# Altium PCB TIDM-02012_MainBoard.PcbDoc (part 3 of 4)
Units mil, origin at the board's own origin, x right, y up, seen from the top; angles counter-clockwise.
Board outline 6550 x 5100 mil, 4 copper layers (Top Layer, Layer 1, Layer 2, Bottom Layer), stack 81.2 mil thick; 300 components, 157 nets, 916 pads, 350 vias.
Unrouted connection lines stored in the file: 93.
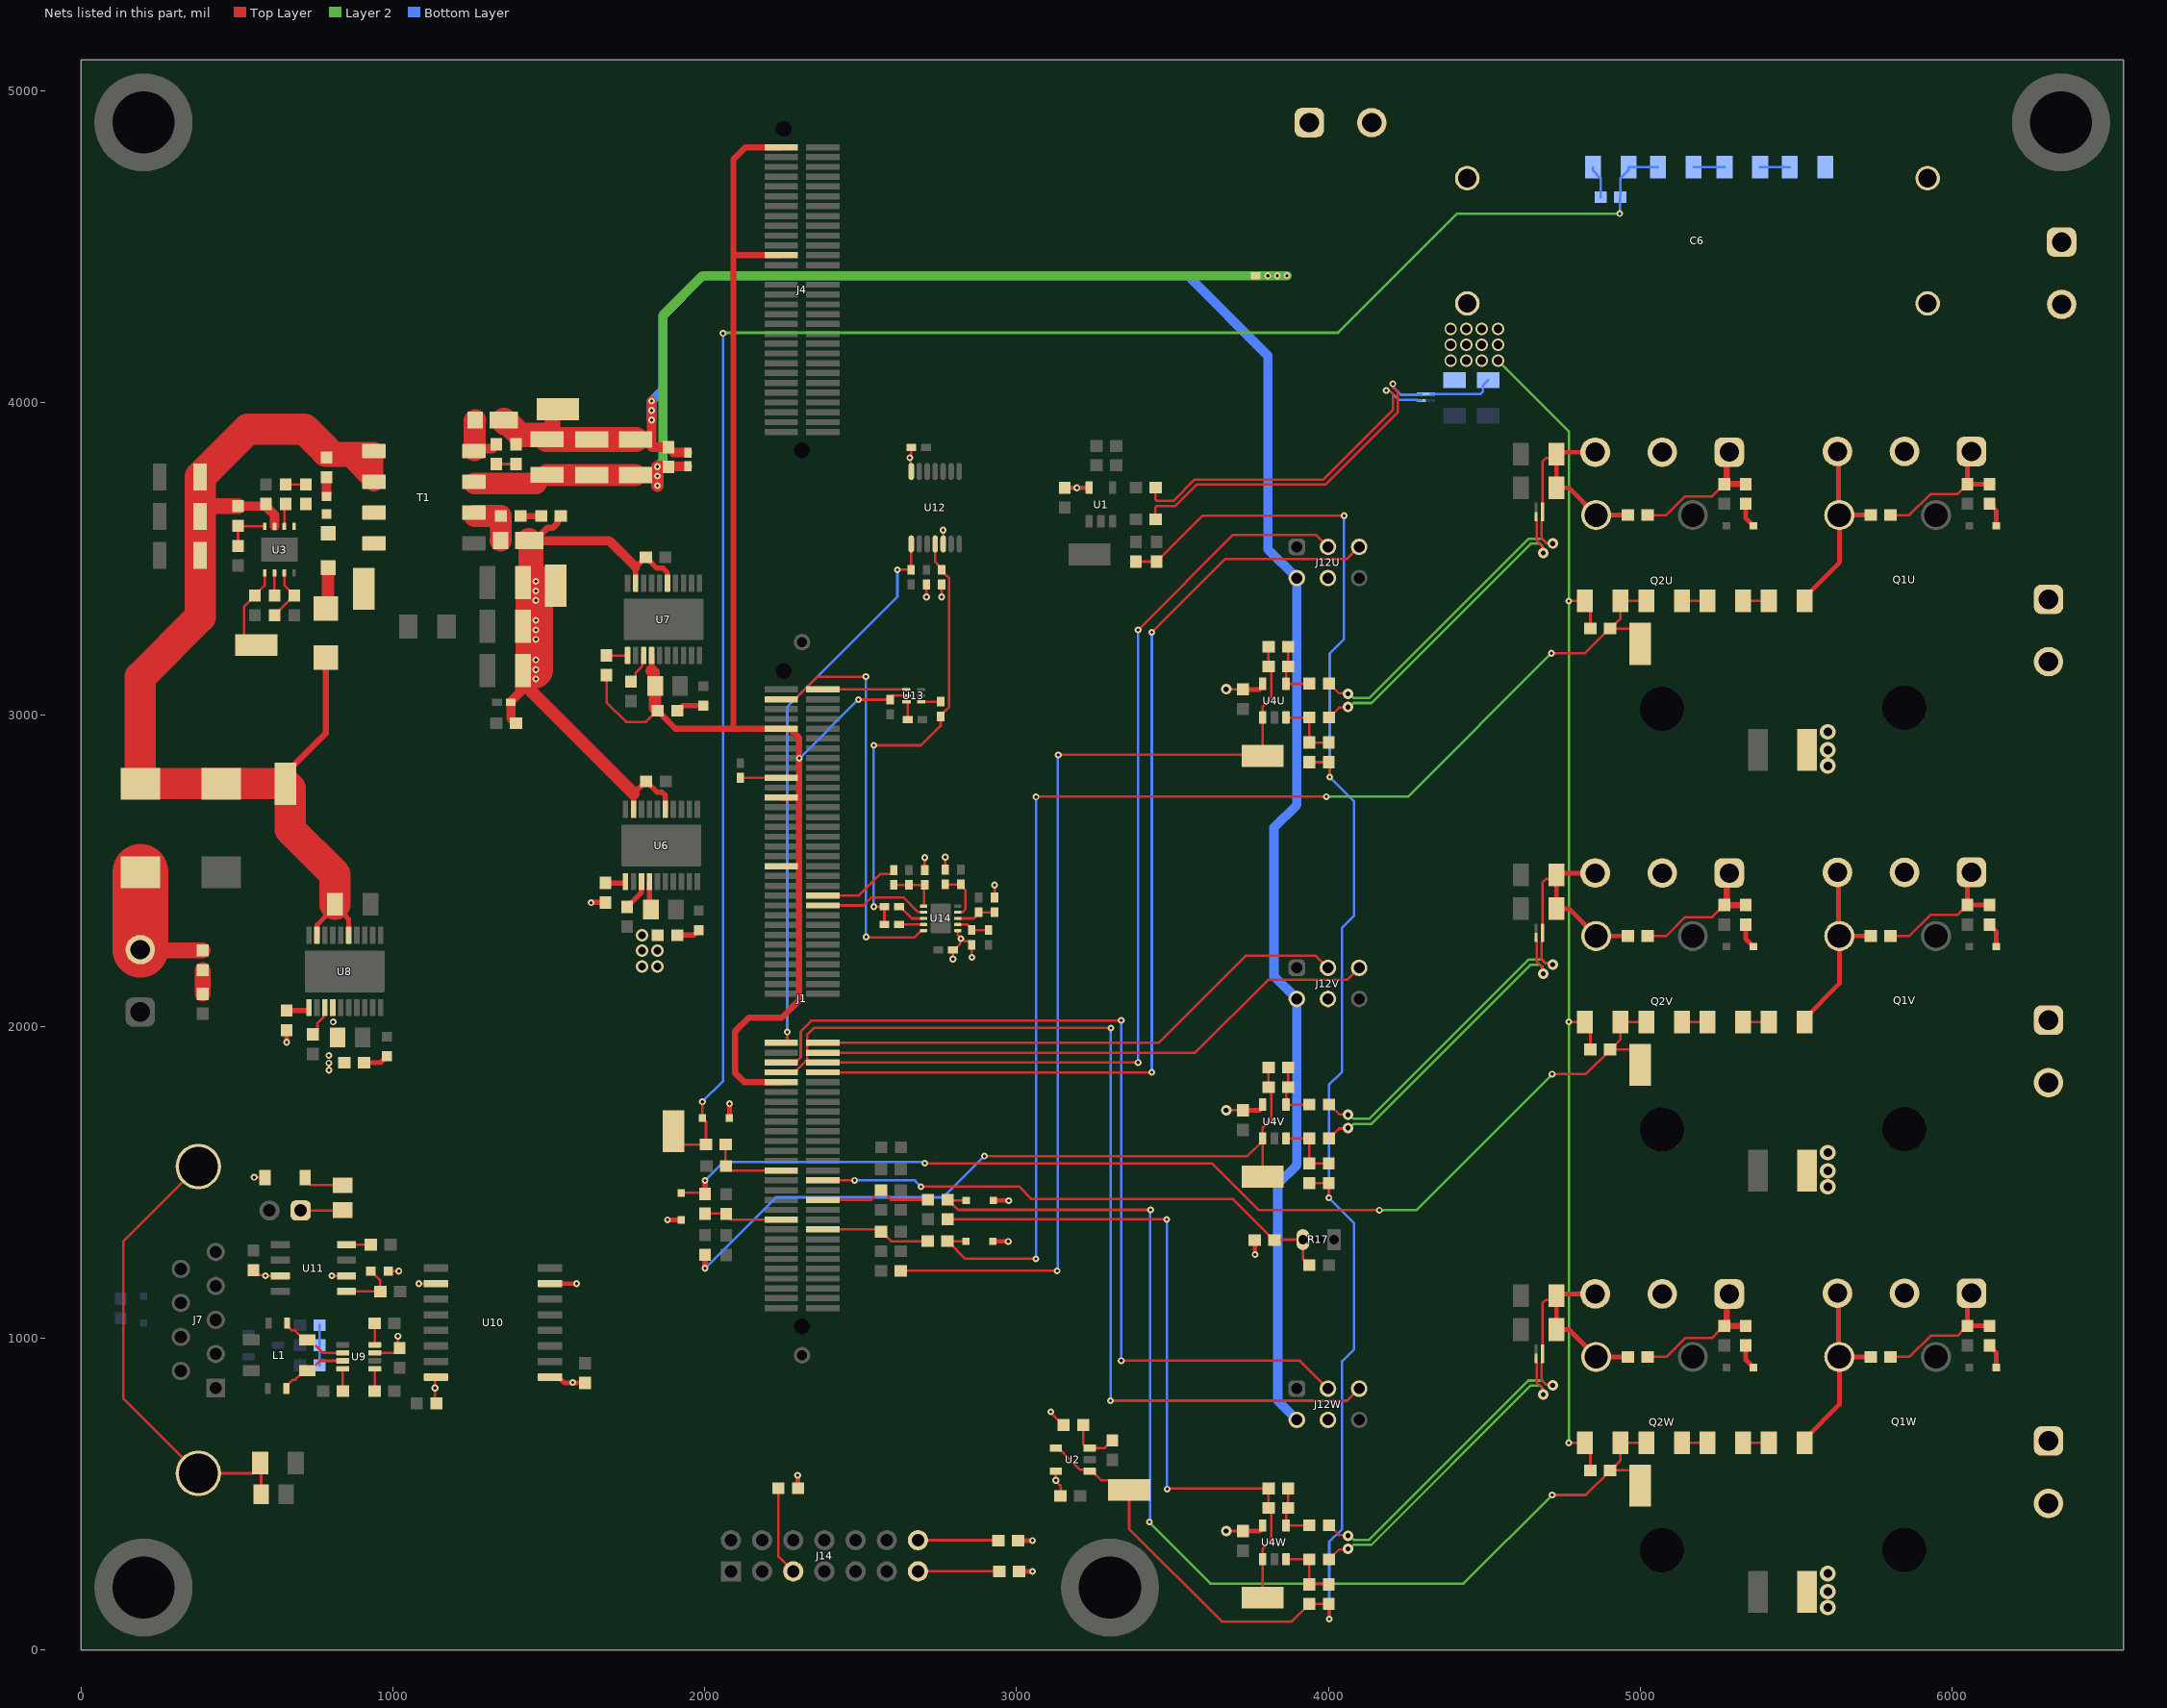
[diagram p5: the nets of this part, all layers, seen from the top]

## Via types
v1: diameter 22, hole 10, Top Layer to Bottom Layer, tented both sides, 245 vias
v2: diameter 40, hole 28, Top Layer to Bottom Layer, tented both sides, 60 vias
v3: diameter 34, hole 16, Top Layer to Bottom Layer, tented both sides, 22 vias
v4: diameter 22, hole 10, Top Layer to Bottom Layer, 9 vias
v5: diameter 50, hole 28, Top Layer to Bottom Layer, tented both sides, 9 vias
v6: diameter 40, hole 25, Top Layer to Bottom Layer, tented both sides, 5 vias

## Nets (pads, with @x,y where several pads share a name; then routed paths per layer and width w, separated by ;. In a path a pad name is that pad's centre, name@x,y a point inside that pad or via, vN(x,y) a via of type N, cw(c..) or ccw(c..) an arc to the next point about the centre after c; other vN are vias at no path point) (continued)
NetC5_1: C5.1 D1.2 R8.1 R11.2 R75.1 TP1.1 | length 6054.7
  Top Layer w8: TP1.1@1899.54,1664.1 1899.54,1652 1930.54,1621 R75.1@2004,1621 2004,1694.39 D1.2@1992.39,1706 v1(1992.39,1758.11)
  Layer 2 w8: v1(2059,4223) 2061.08,4225.08 4030.93,4225.08 4412.85,4607 v1(4935,4607)
  Bottom Layer w8: v1(1992.39,1758.11) 2059,1824.72 v1(2059,4223) ; v1(4935,4607) 4935,4658.5 C5.1@4936.5,4660 4936.5,4719.69 4962.55,4745.75 R11.2@4962.55,4756.57 R8.1@5057.36,4756.57
NetC12_1: C12.1 R18.1 | length 63.2
  Top Layer w8: C12.1@1331.69,3803.76 R18.1@1394.84,3803.76
NetC12_2: C12.2 D3.2 T1.5 | length 179.9
  Top Layer w30: T1.5@1259.55,3845.02 1262.15,3847.62 1267.58,3853.05 1318.97,3853.05 1331.69,3865.77 C12.2@1331.69,3866.75
  Top Layer w70: T1.5@1262.15,3847.62 1262.15,3942.77 D3.2@1264.3,3944.93
NetC18U_1: C18U.1 R29U.2 R43U.1 TP5U.1 U4U.1 | length 3180.4
  Top Layer w8: R43U.1@2628.5,1216 v4(3130.52,1216) ; v4(3133.78,2871) 3786.41,2871 TP5U.1@3789.6,2867.81 U4U.1@3789.6,2990.82 3789.6,3026.05 3816.84,3053.29 3816.84,3146.61 R29U.2@3808.5,3154.95 C18U.1@3808.5,3217.95
  Bottom Layer w8: v4(3130.52,1216) 3132.15,1217.63 3132.15,2869.37 v4(3133.78,2871)
NetC18U_2: C18U.2 R29U.1 R31U.2 U4U.4 | length 196.8
  Top Layer w8: C18U.2@3871.5,3217.95 R29U.1@3871.5,3154.95 3864.4,3147.86 U4U.4@3864.4,3099.09 3938.13,3099.09 R31U.2@3939,3099.95
NetC18V_1: C18V.1 R29V.2 R43V.1 TP5V.1 U4V.1 | length 2366.3
  Top Layer w8: v1(2897.21,1583.98) 3740.64,1583.98 U4V.1@3789.6,1632.94 ; TP5V.1@3789.6,1517.81 U4V.1@3789.6,1632.94 ; C18V.1@3808.5,1867.95 R29V.2@3808.5,1804.95 3816.84,1796.61 3816.84,1703.29 3789.6,1676.05 U4V.1@3789.6,1640.82 U4V.1@3789.6,1632.94
  Top Layer w20: v1(2001,1224.07) R43V.1@2001,1267.5
  Bottom Layer w8: v1(2001,1224.07) 2228.58,1451.65 2764.88,1451.65 v1(2897.21,1583.98)
NetC18V_2: C18V.2 R29V.1 R31V.2 U4V.4 | length 196.8
  Top Layer w8: C18V.2@3871.5,1867.95 R29V.1@3871.5,1804.95 3864.4,1797.86 U4V.4@3864.4,1749.09 3938.13,1749.09 R31V.2@3939,1749.95
NetC18W_1: C18W.1 R29W.2 R43W.1 TP5W.1 U4W.1 | length 2260.5
  Top Layer w8: R43W.1@2778.94,1381.41 v4@3482,1381.41 ; v4(3483,516) 3484.95,517.95 C18W.1@3808.5,517.95 R29W.2@3808.5,454.95 3816.84,446.61 3816.84,353.29 3789.6,326.05 U4W.1@3789.6,290.82 TP5W.1@3789.6,167.81 TP5W.1@3790.2,168.41
  Bottom Layer w8: v4(3482,1381) 3482.5,1380.5 3482.5,516.5 v4(3483,516)
NetC18W_2: C18W.2 R29W.1 R31W.2 U4W.4 | length 196.8
  Top Layer w8: C18W.2@3871.5,517.95 R29W.1@3871.5,454.95 3864.4,447.86 U4W.4@3864.4,399.09 3938.13,399.09 R31W.2@3939,399.95
NetC19U_1: C19U.1 D7U.2 R28U.1 R30U.2 R45U.1 TP4U.1 | length 4224.7
  Top Layer w8: R45U.1@2778.02,1311.27 2779.01,1311.27 R45U.1@2779.48,1310.79 ; D7U.2@2837.69,1310.79 R45U.1@2779.48,1310.79 ; v4@3062.39,1255.02 2835.26,1255.02 R45U.1@2779.48,1310.79 ; v4(3062.62,2735.99) 3063.63,2737 v4(3993.78,2737) ; v1(4715.99,3197.01) 4823.73,3197.01 4902.66,3275.94 C19U.1@4903.64,3275.94 C19U.1@4904.63,3275.94 ; TP4U.1@5000.1,3226.72 5000.1,3244.94 4969.1,3275.94 C19U.1@4904.63,3275.94 ; R28U.1@5019.78,3364.52 R30U.2@4937.11,3364.52 4937.11,3308.42 C19U.1@4904.63,3275.94
  Layer 2 w8: v4(3993.78,2737) 4255.98,2737 v1(4715.99,3197.01)
  Bottom Layer w8: v4(3062.39,1254.14) 3062.62,1254.38 v4(3062.62,2735.99)
NetC19V_1: C19V.1 D7V.2 R28V.1 R30V.2 R45V.1 TP4V.1 | length 3638.4
  Top Layer w8: D7V.2@1925.13,1465.8 1997.79,1465.8 R45V.1@2001,1462.58 ; v1(2705.72,1561.53) 2706.26,1560.98 3626.96,1560.98 3777.44,1410.5 v1(4163.84,1410.5) ; v1(4717.96,1847.01) 4825.7,1847.01 C19V.1@4904.63,1925.94 ; C19V.1@4903.64,1925.94 C19V.1@4904.63,1925.94 ; TP4V.1@5000.1,1876.72 5000.1,1894.94 4969.1,1925.94 C19V.1@4904.63,1925.94 ; R28V.1@5019.78,2014.52 R30V.2@4937.11,2014.52 4937.11,1958.42 C19V.1@4904.63,1925.94
  Top Layer w20: R45V.1@2001,1462.58 v1(2001,1506.02)
  Layer 2 w8: v1(4163.84,1410.5) 4281.45,1410.5 v1(4717.96,1847.01)
  Bottom Layer w8: v1(2001,1506.02) 2059.98,1565 2702.25,1565 v1(2705.72,1561.53)
NetC19W_1: C19W.1 D7W.2 R28W.1 R30W.2 R45W.1 TP4W.1 | length 3747.5
  Top Layer w8: R45W.1@2778.94,1443.92 2779.93,1443.92 R45W.1@2781.85,1442 ; D7W.2@2838.69,1442 R45W.1@2781.85,1442 ; v4(3429.82,1411.5) 2812.35,1411.5 R45W.1@2781.85,1442 ; v1(4717.96,497.01) 4825.7,497.01 C19W.1@4904.63,575.94 ; C19W.1@4903.64,575.94 C19W.1@4904.63,575.94 ; TP4W.1@5000.1,526.72 5000.1,544.94 4969.1,575.94 C19W.1@4904.63,575.94 ; R28W.1@5019.78,664.52 R30W.2@4937.11,664.52 4937.11,608.42 C19W.1@4904.63,575.94
  Layer 2 w8: v4(3426.19,410.47) 3426.19,408.81 3622,213 4433.95,213 v1(4717.96,497.01)
  Bottom Layer w8: v4(3426.19,410.47) 3428.01,412.29 3428.01,1409.68 v4(3429.82,1411.5)
NetC21U_1: C21U.1 R32U.2 R33U.2 U4U.3 | length 217.9
  Top Layer w8: U4U.3@3864.4,2990.82 R32U.2@3939,2990.82 R33U.2@3939,2910.5 C21U.1@4001.99,2910.5
NetC21V_1: C21V.1 R32V.2 R33V.2 U4V.3 | length 217.9
  Top Layer w8: U4V.3@3864.4,1640.82 R32V.2@3939,1640.82 R33V.2@3939,1560.5 C21V.1@4001.99,1560.5
NetC21W_1: C21W.1 R32W.2 R33W.2 U4W.3 | length 217.9
  Top Layer w8: U4W.3@3864.4,290.82 R32W.2@3939,290.82 R33W.2@3939,210.5 C21W.1@4001.99,210.5
NetC27_1: C27.1 D9.2 J5.2 | length 449.7
  Top Layer w50: J5.2@190,2246.15 192.37,2243.78 C27.1@389.97,2243.78
  Top Layer w180: J5.2@190,2246.15 D9.2@190,2494.87
NetC27_2: C27.2 C34.1 | length 76.8
  Top Layer w50: C34.1@389.97,2104 C27.2@389.97,2180.79
NetC31_1: C31.1 U6.3 | length 100.5
  Top Layer w17: C31.1@1750.73,2383 1750.73,2383.99 1796.95,2430.21 1796.95,2463.99 U6.3@1797.18,2464.22
NetC32_1: C32.1 R19.1 | length 62.3
  Top Layer w30: C32.1@786.82,3699.36 R19.1@786.82,3761.65
NetC32_2: C32.2 D18.2 R37.2 T1.1 T1.2 TP6.1 U3.1
NetC33_1: C33.1 R21.1 | length 66.2
  Top Layer w20: C33.1@1409.49,3637.4 1409.73,3637.16 1475.26,3637.16 R21.1@1475.5,3636.91
NetC33_2: C33.2 D10.2 T1.7 | length 163.9
  Top Layer w70: T1.7@1262.15,3637.4 C33.2@1346.5,3637.4 1346.5,3559.27 D10.2@1345.49,3558.27
NetC36_1: C36.1 TP9.1 U3.5 | length 280.8
  Top Layer w8: TP9.1@562,3223 553,3223 522,3254 522,3345.71 557.34,3381.05 C36.1@557.34,3382.03 557.34,3383.02 588.76,3414.43 U3.5@588.76,3454.33
NetC42_1: C42.1 U7.3 | length 100.1
  Top Layer w8: C42.1@1763.61,3106.18 1778.32,3120.88 1778.32,3134.17 1799.34,3155.19 1799.34,3184.81 U7.3@1804.07,3189.54
NetC46_1: C46.1 U8.3 | length 117.6
  Top Layer w8: C46.1@743.26,1974.7 757.96,1989.4 757.96,2009.97 767,2019 767.17,2019 776.92,2028.75 776.92,2055.4 U8.3@781.65,2060.14
  Top Layer w16: C46.1@743.26,1974.7 743.26,1975.68 C46.1@753.96,1986.38
NetC48_2: C48.2 R50.1 R52.2 | length 129.1
  Bottom Layer w8: R50.1@764.99,912.85 C48.2@764.99,977.6 R52.2@764.99,1042
NetC55_1: C55.1 U13.3 | length 60.1
  Top Layer w8: U13.3@2646.98,3041.11 2649.86,3041.11 2650.78,3040.19 C55.1@2650.78,2984.32
NetC57_1: C57.1 R65.1 U14.2 | length 108.3
  Top Layer w8: U14.2@2811.93,2326.78 2842.94,2326.78 2856.72,2313 R65.1@2856.72,2309.06 C57.1@2910.58,2309.06
NetC58_1: C58.1 R70.1 U14.4 | length 164.3
  Top Layer w8: R70.1@2771.43,2455.46 C58.1@2821.77,2455.46 2821.77,2451.52 2836.22,2437.07 2836.22,2375.84 2827.46,2367.07 2812.85,2367.07 U14.4@2811.93,2366.15
NetD2U_2: D2U.2 R13U.1 | length 79.7
  Top Layer w15: R13U.1@6120.33,3676.48 6120.33,3675.5 6142.45,3653.38 D2U.2@6142.45,3605.95
NetD2V_2: D2V.2 R13V.1 | length 79.7
  Top Layer w15: R13V.1@6120.33,2326.48 6120.33,2325.5 6142.45,2303.38 D2V.2@6142.45,2255.95
NetD2W_2: D2W.2 R13W.1 | length 79.7
  Top Layer w15: R13W.1@6120.33,976.48 6120.33,975.5 6142.45,953.38 D2W.2@6142.45,905.95
NetD5U_2: D5U.2 R20U.1 | length 80.7
  Top Layer w15: R20U.1@5338.84,3676.48 5338.84,3630.56 D5U.2@5363.44,3605.95
NetD5V_2: D5V.2 R20V.1 | length 80.7
  Top Layer w15: R20V.1@5338.84,2326.48 5338.84,2280.56 D5V.2@5363.44,2255.95
NetD5W_2: D5W.2 R20W.1 | length 80.7
  Top Layer w15: R20W.1@5338.84,976.48 5338.84,930.56 D5W.2@5363.44,905.95
NetD6_1: D6.1 D18.1 | length 133.8
  Top Layer w40: D6.1@784.49,3340.74 792.3,3348.55 D18.1@792.3,3471.32
NetD12_2: D12.2 R42.1 | length 75.3
  Top Layer w17: R42.1@1912.34,2292.81 1965.39,2292.81 D12.2@1981.14,2308.56
NetD13_2: D13.2 R47.1 | length 90.1
  Top Layer w17: R47.1@1912.34,3012.94 1913.32,3012.94 1929.07,3028.69 D13.2@1995.9,3028.69
NetD15_1: D15.1 R56.2 | length 133.4
  Top Layer w8: D15.1@718.74,1514.96 718.74,1508.95 737.1,1490.59 R56.2@838.51,1490.59
NetD17_2: D17.2 R74.1 | length 82.4
  Top Layer w16: R74.1@907.09,1883.22 959.72,1883.22 D17.2@980.73,1904.23
NetJ1_102: J1.102 R79.1 | length 131.1
  Top Layer w8: R79.1@2114,2797.48 J1.102@2245.14,2797.48
NetJ6_1: J6.1 R56.1 | length 134.7
  Top Layer w8: J6.1@704.27,1409.45 837.38,1409.45 R56.1@838.51,1410.59
NetJ14_5: J14.5 R76.2 | length 286.7
  Top Layer w8: R76.2@2236.5,519 2236.5,299.5 J14.5@2284,252
NetJ14_13: J14.13 R78.2 | length 261
  Top Layer w8: J14.13@2684,252 R78.2@2945.01,252
NetJ14_14: J14.14 R77.1 | length 258.5
  Top Layer w8: J14.14@2684,352 2941.05,352 R77.1@2942.06,350.99
NetL1_1: L1.1 R54.1 U9.7 | length 222.9
  Top Layer w8: R54.1@658.09,838.21 658.09,846.09 678.48,866.47 686.75,866.47 716.28,896 L1.1@725.13,896 733.99,896 765.41,927.42 U9.7@839.39,927.42
NetL1_2: L1.2 R49.1 U9.6 | length 222.9
  Top Layer w8: R49.1@660.57,1048.21 660.57,1040.34 675.91,1025 685.7,1025 716.28,994.43 L1.2@725.13,994.43 733.99,994.43 775.41,953.01 U9.6@839.39,953.01
NetQ1U_1: Q1U.1 R13U.2 R15U.2 R16U.2 | length 469.3
  Top Layer w8: R16U.2@5802.99,3640 5863.82,3640 5931.8,3707.98 6018.26,3707.98 6034.07,3723.79 6035.06,3723.79 6049.76,3738.49 R15U.2@6049.76,3739.47
  Top Layer w15: Q1U.1@6063,3844.2 6049.76,3830.96 R15U.2@6049.76,3739.47 R13U.2@6120.33,3739.47
NetQ1V_1: Q1V.1 R13V.2 R15V.2 R16V.2 | length 469.3
  Top Layer w8: R16V.2@5802.99,2290 5863.82,2290 5931.8,2357.98 6018.26,2357.98 6034.07,2373.79 6035.06,2373.79 6049.76,2388.49 R15V.2@6049.76,2389.47
  Top Layer w15: Q1V.1@6063,2494.2 6049.76,2480.96 R15V.2@6049.76,2389.47 R13V.2@6120.33,2389.47
NetQ1W_1: Q1W.1 R13W.2 R15W.2 R16W.2 | length 469.3
  Top Layer w8: R16W.2@5802.99,940 5863.82,940 5931.8,1007.98 6018.26,1007.98 6034.07,1023.79 6035.06,1023.79 6049.76,1038.49 R15W.2@6049.76,1039.47
  Top Layer w15: Q1W.1@6063,1144.2 6049.76,1130.96 R15W.2@6049.76,1039.47 R13W.2@6120.33,1039.47
NetQ2U_1: Q2U.1 R20U.2 R22U.2 R23U.2 | length 465.6
  Top Layer w8: R23U.2@5023.99,3640 5083.82,3640 5144.05,3700.23 5230.86,3700.23 5254.42,3723.79 5255.4,3723.79 5270.1,3738.49 R22U.2@5270.1,3739.47
  Top Layer w20: Q2U.1@5285.99,3841.83 5278.05,3833.89 5278.05,3747.41 R22U.2@5270.1,3739.47 R20U.2@5338.84,3739.47
NetQ2V_1: Q2V.1 R20V.2 R22V.2 R23V.2 | length 465.6
  Top Layer w8: R23V.2@5023.99,2290 5083.82,2290 5144.05,2350.23 5230.86,2350.23 5254.42,2373.79 5255.4,2373.79 5270.1,2388.49 R22V.2@5270.1,2389.47
  Top Layer w20: Q2V.1@5285.99,2491.83 5278.05,2483.89 5278.05,2397.41 R22V.2@5270.1,2389.47 R20V.2@5338.84,2389.47
NetQ2W_1: Q2W.1 R20W.2 R22W.2 R23W.2 | length 465.6
  Top Layer w8: R23W.2@5023.99,940 5083.82,940 5144.05,1000.23 5230.86,1000.23 5254.42,1023.79 5255.4,1023.79 5270.1,1038.49 R22W.2@5270.1,1039.47
  Top Layer w20: Q2W.1@5285.99,1141.83 5278.05,1133.89 5278.05,1047.41 R22W.2@5270.1,1039.47 R20W.2@5338.84,1039.47
NetR5_1: R5.1 R12.2 U2.3 | length 170.4
  Top Layer w8: R5.1@3213.97,721.37 3213.97,660.54 3226.73,647.77 U2.3@3234.61,647.77 3282.88,647.77 3291.79,656.68 3292.77,656.68 3307.47,671.38 R12.2@3307.47,672.37
NetR6_1: R6.1 R7.2 | length 94.2
  Bottom Layer w8: R7.2@5385.07,4756.57 R6.1@5479.25,4756.57
NetR7_1: R7.1 R8.2 | length 99.4
  Bottom Layer w8: R8.2@5171.53,4756.57 R7.1@5270.9,4756.57
NetR26U_1: R26U.1 R27U.2 | length 82
  Top Layer w8: R27U.2@5330.81,3364.52 R26U.1@5412.86,3364.52
NetR26V_1: R26V.1 R27V.2 | length 82
  Top Layer w8: R27V.2@5330.81,2014.52 R26V.1@5412.86,2014.52
NetR26W_1: R26W.1 R27W.2 | length 82
  Top Layer w8: R27W.2@5330.81,664.52 R26W.1@5412.86,664.52
NetR27U_1: R27U.1 R28U.2 | length 82.7
  Top Layer w8: R28U.2@5133.96,3364.52 R27U.1@5216.64,3364.52
NetR27V_1: R27V.1 R28V.2 | length 82.7
  Top Layer w8: R28V.2@5133.96,2014.52 R27V.1@5216.64,2014.52
NetR27W_1: R27W.1 R28W.2 | length 82.7
  Top Layer w8: R28W.2@5133.96,664.52 R27W.1@5216.64,664.52
NetR34_1: R34.1 R38.2 U3.4 | length 150.9
  Top Layer w8: R38.2@503.34,3541.26 R34.1@503.34,3605.91 505.31,3603.94 U3.4@588.76,3603.94
NetR35_1: R35.1 R39.2 U3.7 | length 175.6
  Top Layer w8: R35.1@620.22,3319.04 620.22,3320.02 666.55,3366.35 668.54,3366.35 683.24,3381.05 R39.2@683.24,3382.03 683.24,3383.02 651.75,3414.51 U3.7@651.75,3454.33
NetR35_2: R35.2 U3.6 | length 72.3
  Top Layer w8: R35.2@620.25,3382.06 U3.6@620.25,3454.33
NetR36_1: R36.1 U3.2 | length 73.3
  Top Layer w8: U3.2@651.75,3603.94 651.75,3671.3 R36.1@655.98,3675.53
NetR36_2: R36.2 R37.1 | length 64.7
  Top Layer w8: R36.2@655.98,3738.52 R37.1@720.65,3738.52
NetR41_1: R41.1 U6.1 | length 68.5
  Top Layer w17: R41.1@1681.16,2460.36 1745.64,2460.36 1746,2460.72 U6.1@1746,2464.22
NetR46_1: R46.1 U7.1 | length 67.9
  Top Layer w8: R46.1@1685.04,3189.69 1685.19,3189.54 U7.1@1752.89,3189.54
NetR48_1: R48.1 U8.1 | length 79.5
  Top Layer w16: R48.1@659.59,2051.01 729.61,2051.01 730.47,2051.87 U8.1@730.47,2060.14
NetR51_2: R51.2 U9.1 | length 71.9
  Top Layer w8: R51.2@941.5,830 941.75,830.24 U9.1@941.75,901.83
NetR53_2: R53.2 U9.4 | length 69.6
  Top Layer w8: U9.4@941.75,978.6 R53.2@941.75,1048.21
NetR55_2: R55.2 U9.8 | length 71.8
  Top Layer w8: R55.2@839.39,830 U9.8@839.39,901.83
NetR57_1: R57.1 R58.2 U11.1 | length 186.2
  Top Layer w8: U11.1@851.3,1150 928.95,1150 R58.2@959.72,1150 959.72,1184.22 R57.1@928.95,1214.99
NetR59_2: R59.2 U11.4 | length 77.7
  Top Layer w8: U11.4@851.3,1300 R59.2@928.95,1300
NetR64_1: R64.1 U13.4 | length 62.8
  Top Layer w8: U13.4@2694.22,3041.11 2756.35,3041.11 R64.1@2756.81,3041.57
NetR66_1: R66.1 U14.9 | length 78.2
  Top Layer w8: R66.1@2623.53,2326.94 2623.61,2326.86 2701.62,2326.86 U14.9@2701.7,2326.78
NetR67_1: R67.1 U14.8 | length 93.7
  Top Layer w8: R67.1@2623.53,2383.87 2627.47,2383.87 2664.87,2346.47 U14.8@2701.7,2346.47
NetR68_1: R68.1 R71.2 U14.3 | length 128.2
  Top Layer w8: U14.3@2811.93,2346.47 2862.63,2346.47 2878.37,2362.21 R71.2@2878.37,2366.15 ; R71.2@2878.37,2366.15 R68.1@2929.72,2366.15
NetR69_1: R69.1 R72.2 R73.1 U14.6 | length 170.4
  Top Layer w8: R73.1@2605.9,2454.08 R72.2@2655.12,2454.08 R69.1@2705.72,2454.08 2703.71,2452.07 2703.71,2386.76 2702.79,2385.84 U14.6@2701.7,2385.84
P5V_MCU: C41.1 C54.1 J1.48 J1.84 J1.98 J1.112 J4.158 J4.180 R46.2 R47.2 U7.4 U13.2 | length 5040.2
  Top Layer w8: R46.2@1685.04,3126.69 1685.04,3039.35 1747.83,2976.57 1811.74,2976.57 1820.86,2985.68 1821.09,2985.68 1841.04,3005.63 R47.2@1841.04,3012.94 ; v1(2493.33,3048) C54.1@2595,3048 2595,3051.94 2603.86,3060.8 U13.2@2646.98,3060.8
  Top Layer w17: U7.4@1829.66,3189.54 1829.89,3189.31 1829.89,3140.03
  Top Layer w20: R47.2@1841.04,3021.24 1842.03,3021.24 1859.03,3004.24 1859.03,3002.41 1906.48,2954.96 2092.35,2954.96 ; J1.48@2245.14,1821.1 2127.28,1821.1 2096.84,1851.54 2096.84,1983.84 2141,2028 2247,2028 2303,2084 2303,2514.22 ; J1.84@2245.14,2514.02 2302.79,2514.02 2303,2514.22 ; J1.98@2245.14,2734.49 2303,2734.49 ; J4.158@2245.14,4473.58 2092,4473.58 ; J4.180@2245.14,4820.04 2131.04,4820.04 2092,4781 2092,4473.58 ; 2092,4473.58 2092,2955.31 2092.35,2954.96 ; 2092.35,2954.96 J1.112@2245.14,2954.96 2245.3,2954.8 2272.72,2954.8 2303,2924.52 v1(2303,2860.47) 2303,2734.49 ; 2303,2514.22 2303,2734.49
  Top Layer w40: 1829.66,3140.26 1829.89,3140.03 1836.04,3133.87 1836.04,3096.69 C41.1@1841.04,3091.69 R47.2@1841.04,3021.24
  Bottom Layer w8: v1(2303,2860.47) 2304.4,2860.47 2491.93,3048 v1(2493.33,3048)
PGND: C5.2 C6.1 C6.2 C15.2 C16.2 C17.2 C19U.2 C19V.2 C19W.2 C22.2 D4.2 J3.1 J3.2 NT2.1 R1.1 R2.1 R11.1 R30U.1 R30V.1 R30W.1 R44.2 T1.6 | length 7636.1
  Top Layer w8: v1(4771.34,664.52) R30W.1@4822.93,664.52 4840.65,646.8 C19W.2@4840.65,575.94 ; v1(4771.34,2014.52) R30V.1@4822.93,2014.52 4840.65,1996.8 C19V.2@4840.65,1925.94 ; v1(4771.34,3364.52) R30U.1@4822.93,3364.52 4840.65,3346.8 C19U.2@4840.65,3275.94
  Top Layer w30: C16.2@1778.44,3768.48 1788.88,3778.91 1846.84,3778.91 v1@1846.84,3793.92 ; C22.2@1884.1,3793.99 C22.2@1884.1,3794.97 1885.38,3796.25 1945.25,3796.25 D4.2@1946,3797
  Top Layer w40: v1(1848.13,3795.21) 1882.88,3795.21 C22.2@1884.1,3793.99 ; v1@1848.25,3765.21 v1(1848.36,3734.32)
  Top Layer w70: T1.6@1262.15,3741.07 1457.8,3741.07 ; C15.2@1494.11,3768.64 1494.27,3768.48 C16.2@1778.44,3768.48
  Layer 2 w8: v2(4544.01,4135.68) 4771.34,3908.35 v1(4771.34,3364.52) v1(4771.34,2014.52) v1(4771.34,664.52)
  Layer 2 w30: v1(1848.13,3795.21) 1865.71,3812.78 1865.71,4279.71 1993.81,4407.81 3609.63,4407.81 3806.11,4407.96 3836.11,4407.98 v1(3867,4408) ; v1@1848.26,3795.21 1848.31,3765.21 v1(1848.36,3734.32)
  Bottom Layer w8: NT2.1@4328,4028 4487.81,4028 4495.5,4035.69 4495.5,4055.57 R2.1@4513.02,4073.09 ; R11.1@4848.38,4756.57 4848.38,4745.75 4873.5,4720.63 C5.2@4873.5,4660
  other v1: 1848.13,3765.21 3806.11,4407.77 3836.11,4407.77
  other v2: 4392.51,4135.68 4442.26,4135.68 4492.01,4135.68 4392.51,4186.68 4442.26,4186.68 4492.01,4186.68 4544.01,4186.68 4392.51,4236.68 4442.26,4236.68 4492.01,4236.68 4544.01,4236.68
PWM1A: J1.49 J12U.5 | length 3244.5
  Top Layer w8: J1.49@2379,1852.6 v1@3434,1852.6 ; v1(3433.95,3263.95) 3669.43,3499.43 4060.43,3499.43 J12U.5@4099,3538
  Bottom Layer w8: v1(3434,1853) v1@3433.98,3263.93
PWM1B: J1.51 J12U.3 | length 3150
  Top Layer w8: J1.51@2379,1884.09 v1(3390,1884.09) ; v1(3390,3272) 3694.57,3576.57 3960.43,3576.57 J12U.3@3999,3538
  Bottom Layer w8: v1(3390,1884.09) v1(3390,3272)
PWM2A: J1.53 J12V.5 | length 1832.8
  Top Layer w8: J1.53@2379,1915.59 3573.35,1915.59 3807.18,2149.43 4060.43,2149.43 J12V.5@4099,2188
PWM2B: J1.55 J12V.3 | length 1751.7
  Top Layer w8: J1.55@2379,1947.09 3455,1947.09 3734.49,2226.57 3960.43,2226.57 J12V.3@3999,2188
PWM3A: J1.50 J12W.5 | length 3174
  Top Layer w8: J1.50@2245.14,1852.6 2288.6,1852.6 2328.68,1892.68 2328.68,1972.95 2351.73,1996 v1@3303,1996 ; v1(3301.45,799.43) 4060.43,799.43 J12W.5@4099,838
  Bottom Layer w8: v1(3301.45,799.43) 3302.23,800.2 3302.23,1994.23 v1(3303,1995)
PWM3B: J1.52 J12W.3 | length 2986.3
  Top Layer w8: J1.52@2245.14,1884.09 2291.09,1884.09 2308,1901 2308,1984 2342,2018 v1@3336,2018 ; v1(3336.02,927.87) 3909.13,927.87 J12W.3@3999,838
  Bottom Layer w8: v1(3336.02,927.87) v1(3336,2019)
S_1U: J9U.1 J13U.1 J13U.2 Q1U.3 Q2U.2 R16U.1 R26U.2 | length 629.5
  Top Layer w15: R26U.2@5527.03,3364.52 5527.03,3375.35 5639,3487.31 J9U.1@5639,3640 ; Q1U.3@5633,3844.2 5636,3841.2 5636,3643 J9U.1@5639,3640 ; R16U.1@5740,3640 J9U.1@5639,3640
S_1V: J9V.1 J13V.1 J13V.2 Q1V.3 Q2V.2 R16V.1 R26V.2 | length 629.5
  Top Layer w15: R26V.2@5527.03,2014.52 5527.03,2025.35 5639,2137.31 J9V.1@5639,2290 ; Q1V.3@5633,2494.2 5636,2491.2 5636,2293 J9V.1@5639,2290 ; R16V.1@5740,2290 J9V.1@5639,2290
S_1W: J9W.1 J13W.1 J13W.2 Q1W.3 Q2W.2 R16W.1 R26W.2 | length 629.5
  Top Layer w15: R26W.2@5527.03,664.52 5527.03,675.35 5639,787.31 J9W.1@5639,940 ; Q1W.3@5633,1144.2 5636,1141.2 5636,943 J9W.1@5639,940 ; R16W.1@5740,940 J9W.1@5639,940
S_2U: J11U.1 NT3U.1 Q2U.3 R23U.1 R24U.2 R25U.2 | length 691.2
  Top Layer w8: NT3U.1@4687,3665 4687,3793.04 4687,3811.93 4697.84,3822.77 4718.7,3822.77 R24U.2@4731.86,3835.93
  Top Layer w15: R24U.2@4731.86,3825.1 R25U.2@4731.86,3727.66 4771.34,3727.66 J11U.1@4859,3640 R23U.1@4961,3640 ; R24U.2@4731.86,3835.93 4737.76,3841.83 Q2U.3@4855.99,3841.83
S_2V: J11V.1 NT3V.1 Q2V.3 R23V.1 R24V.2 R25V.2 | length 691.2
  Top Layer w8: NT3V.1@4687,2315 4687,2443.04 4687,2461.93 4697.84,2472.77 4718.7,2472.77 R24V.2@4731.86,2485.93
  Top Layer w15: R24V.2@4731.86,2475.1 R25V.2@4731.86,2377.66 4771.34,2377.66 J11V.1@4859,2290 R23V.1@4961,2290 ; R24V.2@4731.86,2485.93 4737.76,2491.83 Q2V.3@4855.99,2491.83
S_2W: J11W.1 NT3W.1 Q2W.3 R23W.1 R24W.2 R25W.2 | length 691.2
  Top Layer w8: NT3W.1@4687,965 4687,1093.04 4687,1111.93 4697.84,1122.77 4718.7,1122.77 R24W.2@4731.86,1135.93
  Top Layer w15: R24W.2@4731.86,1125.1 R25W.2@4731.86,1027.66 4771.34,1027.66 J11W.1@4859,940 R23W.1@4961,940 ; R24W.2@4731.86,1135.93 4737.76,1141.83 Q2W.3@4855.99,1141.83
SHIELD_GND: C53.1 J7.10 J7.11 R60.2 | length 1492.3
  Top Layer w8: J7.11@375.91,1550.6 135,1309.69 135,807.25 J7.10@375.91,566.35 551.95,566.35 574.27,588.67 574.27,594.08 577.35,591 R60.2@577.35,499.94
Shunt_N: NT2.2 R9.1 | length 1151.1
  Top Layer w8: R9.1@3446,3626.87 3446,3664.85 3450.68,3669.54 3509.63,3669.54 3577.9,3737.81 3990.43,3737.81 4223,3970.37 4223,4035.13 4209.68,4048.45 4209.68,4058.35 v1(4207,4061.03)
  Bottom Layer w8: v1(4207,4061.03) 4209.68,4058.35 4209.68,4048.45 4232.26,4025.87 4283.87,4025.87 4285,4027 4297,4027 NT2.2@4298,4028
Shunt_P: NT1.2 R4.1 | length 1124.6
  Top Layer w8: R4.1@3446,3728.21 3446,3690.22 3450.68,3685.54 3503,3685.54 3571.27,3753.81 3983.81,3753.81 4207,3977 4207,4028.51 4198.36,4037.14 4188.47,4037.14 v1(4185.79,4039.82)
  Bottom Layer w8: v1(4185.79,4039.82) 4188.47,4037.14 4198.36,4037.14 4225.64,4009.87 4283.87,4009.87 4285,4008.74 4297,4008.74 NT1.2@4298,4007.74
ShuntU_N: NT4U.2 R32U.1 | length 1067.3
  Top Layer w8: R32U.1@4001.99,2990.82 4002.98,2990.82 4034.6,3022.44 4061.66,3022.44 v3(4063.6,3024.39) ; NT4U.2@4666,3635 4666,3625 4668.5,3622.5 4668.5,3558.72 4686.53,3540.69 4686.53,3522.3 v3(4689.84,3518.99)
  Layer 2 w8: v3(4063.6,3024.39) 4068.29,3024.39 4081.29,3037.39 4138.12,3037.39 4648.72,3547.99 4679.23,3547.99 4686.53,3540.69 4686.53,3522.3 v3(4689.84,3518.99)
ShuntU_P: NT3U.2 R31U.1 | length 1067.3
  Top Layer w8: R31U.1@4001.99,3099.95 4002.98,3099.95 4034.6,3068.33 4061.66,3068.33 v3(4063.6,3066.39) ; NT3U.2@4687,3635 4687,3625 4684.5,3622.5 4684.5,3565.35 4697.84,3552 4716.23,3552 v3(4719.54,3548.69)
  Layer 2 w8: v3(4063.6,3066.39) 4068.29,3066.39 4081.29,3053.39 4131.49,3053.39 4642.1,3563.99 4685.85,3563.99 4697.84,3552 4716.23,3552 v3(4719.54,3548.69)
ShuntV_N: NT4V.2 R32V.1 | length 1067.3
  Top Layer w8: R32V.1@4001.99,1640.82 4002.98,1640.82 4034.6,1672.44 4061.66,1672.44 v3(4063.6,1674.39) ; NT4V.2@4666,2285 4666,2275 4668.5,2272.5 4668.5,2208.72 4686.53,2190.69 4686.53,2172.3 v3(4689.84,2168.99)
  Layer 2 w8: v3(4063.6,1674.39) 4068.29,1674.39 4081.29,1687.39 4138.12,1687.39 4648.72,2197.99 4679.23,2197.99 4686.53,2190.69 4686.53,2172.3 v3(4689.84,2168.99)
ShuntV_P: NT3V.2 R31V.1 | length 1067.3
  Top Layer w8: R31V.1@4001.99,1749.95 4002.98,1749.95 4034.6,1718.33 4061.66,1718.33 v3(4063.6,1716.39) ; NT3V.2@4687,2285 4687,2275 4684.5,2272.5 4684.5,2215.35 4697.84,2202 4716.23,2202 v3(4719.54,2198.69)
  Layer 2 w8: v3(4063.6,1716.39) 4068.29,1716.39 4081.29,1703.39 4131.49,1703.39 4642.1,2213.99 4685.85,2213.99 4697.84,2202 4716.23,2202 v3(4719.54,2198.69)
ShuntW_N: NT4W.2 R32W.1 | length 1067.3
  Top Layer w8: R32W.1@4001.99,290.82 4002.98,290.82 4034.6,322.44 4061.66,322.44 v3(4063.6,324.39) ; NT4W.2@4666,935 4666,925 4668.5,922.5 4668.5,858.72 4686.53,840.69 4686.53,822.3 v3(4689.84,818.99)
  Layer 2 w8: v3(4063.6,324.39) 4068.29,324.39 4081.29,337.39 4138.12,337.39 4648.72,847.99 4679.23,847.99 4686.53,840.69 4686.53,822.3 v3(4689.84,818.99)
ShuntW_P: NT3W.2 R31W.1 | length 1067.3
  Top Layer w8: R31W.1@4001.99,399.95 4002.98,399.95 4034.6,368.33 4061.66,368.33 v3(4063.6,366.39) ; NT3W.2@4687,935 4687,925 4684.5,922.5 4684.5,865.35 4697.84,852 4716.23,852 v3(4719.54,848.69)
  Layer 2 w8: v3(4063.6,366.39) 4068.29,366.39 4081.29,353.39 4131.49,353.39 4642.1,863.99 4685.85,863.99 4697.84,852 4716.23,852 v3(4719.54,848.69)
SYSTEM_DISABLE_FET_SUPPLY: J1.56 R63.2 U12.1 | length 1807.3
  Top Layer w8: J1.56@2245.14,1947.09 2258.92,1947.09 2264.76,1952.93 v1(2264.76,1981.77) ; v1(2618.04,3464.82) R63.2@2662.42,3464.82 U12.1@2662.42,3547.46
  Bottom Layer w8: v1(2264.76,1981.77) 2264.76,3024.91 2618.04,3378.19 v1(2618.04,3464.82)
SYSTEM_WATCHDOG_DISABLE: J1.77 R73.2 | length 263.1
  Top Layer w8: J1.77@2379,2419.53 2493.33,2419.53 2563.38,2489.58 2598.09,2489.58 2605.9,2497.39 R73.2@2605.9,2501.32
SYSTEM_WATCHDOG_OUT: J1.75 U14.7 | length 352.8
  Top Layer w8: J1.75@2379,2388.03 2508.71,2388.03 2534.11,2413.43 2638.5,2413.43 2684.86,2367.07 2700.77,2367.07 U14.7@2701.7,2366.15
Temp: C11.2 J1.27 R14.1 R17.2 | length 1710.9
  Top Layer w8: J1.27@2379,1506.14 v1(2480.52,1506.14) ; v1(2693.81,1486) 2694.81,1487 3007.81,1487 3048.71,1446.1 3694.64,1446.1 3826.02,1314.73 R14.1@3827,1314.73 3828.38,1316.11 R17.2@3918.46,1316.11 3918.46,1255.02 3923.31,1250.16 3923.31,1249.18 3938.02,1234.48 C11.2@3939,1234.48
  Bottom Layer w8: v1(2480.52,1506.14) 2673.67,1506.14 v1(2693.81,1486)
V_bias_1v65: C4.2 C21U.2 C21V.2 C21W.2 R10.1 R33U.1 R33V.1 R33W.1 TP3.1 U2.1 U2.4 | length 5895.7
  Top Layer w8: U2.4@3126.34,647.77 3134.22,647.77 3170.63,611.36 3170.63,610.37 3202.92,578.08 3229.5,578.08 U2.1@3234.61,572.97 3242.48,572.97 3271.38,544.07 3330.45,544.07 TP3.1@3361.45,513.07 3361.45,388.04 3658.65,90.84 3883.32,90.84 3939,146.52 R33W.1@3939,147.5 C21W.2@4001.99,147.5 4002.98,146.52 v1(4002.98,99) ; R10.1@3382.44,3490.91 C4.2@3448.95,3490.91 3448.95,3491.89 3463.65,3506.59 3464.63,3506.59 3596.05,3638.01 v1(4050.61,3638.01) ; R33V.1@3939,1497.5 C21V.2@4001.99,1497.5 v1(4002,1450) ; R33U.1@3939,2847.5 C21U.2@4001.99,2847.5 4004.5,2845 v1(4004.5,2800)
  Bottom Layer w8: v1(4002.98,99) 4002.98,346.77 4044.43,388.22 4044.43,925.95 4083,964.53 4083,1369 v1(4002,1450) 4002,1812.51 4044.43,1854.93 4044.43,2316.81 4083,2355.39 4083,2721.5 v1(4004.5,2800) 4004.5,3195.95 4050.61,3242.06 v1(4050.61,3638.01)
Vbat_prot: C13.2 C14.2 C28.1 C37.2 C44.1 D6.2 D9.1 D11.1 R19.2 R34.2 T1.3 T1.4 TP7.1 U3.3 U8.15 U8.19 | length 3843.5
  Top Layer w16: U8.19@756.06,2292.42 756.79,2293.15 756.79,2325.46 C44.1@794.18,2362.85 ; C44.1@839.55,2362.85 858.42,2343.98 U8.15@858.42,2292.42
  Top Layer w20: TP7.1@655.24,2778.34 655.24,2810.84 784.49,2940.09 D6.2@784.49,3183.26
  Top Layer w30: R34.2@503.34,3668.9 586.32,3668.9 588.27,3670.85 589.26,3670.85 592.96,3674.55 C28.1@592.96,3675.53 596.66,3671.83 596.66,3663.94 620.22,3640.37 U3.3@620.22,3609.87 ; U3.3@620.25,3603.94 U3.3@620.25,3609.84
  Top Layer w50: 381.95,3687 400.05,3668.9 R34.2@503.34,3668.9
  Top Layer w60: R19.2@786.82,3824.65 860.79,3824.65 938.84,3746.6 T1.3@939.47,3746.6 T1.4@939.47,3845.02 786.82,3845.02
  Top Layer w100: 786.82,3845.02 715.84,3916 535.21,3916 C37.2@381.95,3762.74 381.95,3687 C14.2@381.95,3636.05 C13.2@381.95,3510.85 381.95,3312.95 190,3121 D9.1@190,2778.34 D11.1@448.97,2778.34 TP7.1@655.24,2778.34 670.24,2763.34 670.24,2631.76 814.21,2487.79 C44.1@814.21,2391.27
VBUS: C6.3 C6.4 C8U.1 C8V.1 C8W.1 J2.1 J2.2 Q1U.2 Q1V.2 Q1W.2 R6.2
  other v5: 5601.88,135.77 5601.88,186.77 5601.88,245.03 5601.88,1485.77 5601.88,1536.77 5601.88,1595.03 5601.88,2835.77 5601.88,2886.77 5601.88,2945.03
VCC5_LV: C45.1 C47.1 C49.1 C51.1 D15.2 R48.2 R57.2 R74.2 U8.4 U9.3 U10.10 U10.16 U11.2 U11.7 | length 517.4
  Top Layer w8: C51.1@552.75,1218.31 552.75,1217.32 567.45,1202.62 588.38,1202.62 v1(591,1200) U11.7@638.7,1200 ; v1(555,1516) 588.76,1516 D15.2@589.8,1514.96 ; v1(804.06,1200) U11.2@851.3,1200 ; U9.3@941.75,953.01 1006.3,953.01 1021,967.71 C47.1@1021,967.99 ; R57.2@984.95,1214.99 v1(1019,1215) ; C47.1@1016.12,967.99 v1(1016.12,1006.46) ; v1(1083.58,1175) U10.10@1137.93,1175 ; U10.16@1137.93,875 1135,872.07 v1(1135,840) 1135,795.5 C49.1@1139.5,791
  Top Layer w16: v1(659,1949) 659.3,1949.3 659.3,1987.72 R48.2@659.59,1988.02 ; U8.4@807.24,2060.14 U8.4@807.93,2059.44 ; R74.2@843.11,1883.22 R74.2@844.09,1883.22
  other v1: 794.45,1859.55 794.42,1882.53 794.42,1906.78 808.3,2014.24
VCC6: C23.2 C24.2 C25.1 C29.2 C30.2 C40.1 D8.1 D10.1 R21.2 TP8.1 U6.15 U6.19 U7.15 U7.19 | length 2375.1
  Top Layer w8: C29.2@1417.45,3111.95 1420.19,3114.69 v1(1458.48,3114.69) ; C29.2@1417.45,3141.95 1420.19,3144.69 v1(1458.48,3144.69) ; C29.2@1417.45,3172.95 1420.19,3175.69 v1(1458.48,3175.69) ; C24.2@1417.45,3238.64 1420.19,3241.38 v1(1458.48,3241.38) ; C24.2@1417.45,3268.64 1420.19,3271.38 v1(1458.48,3271.38) ; C24.2@1417.45,3299.64 1420.19,3302.38 v1(1458.48,3302.38) ; 1417.45,3363.84 1420.19,3366.58 v1(1458.48,3366.58) ; C23.2@1417.45,3393.84 1420.19,3396.58 v1(1458.48,3396.58) ; C23.2@1417.45,3424.84 1420.19,3427.58 v1(1458.48,3427.58)
  Top Layer w17: U6.19@1771.59,2696.5 1771.59,2746.55 1810.96,2785.92 C25.1@1811.95,2785.92 1812.93,2785.92 1848.13,2750.72 1863.65,2750.72 1873.95,2740.42 U6.15@1873.95,2696.5 ; U7.19@1778.48,3421.83 1778.48,3473.1 1810.06,3504.69 C40.1@1811.04,3504.69 1812.03,3504.69 1847.23,3469.48 1866.2,3469.48 1880.61,3455.08 1880.61,3422.06 U7.15@1880.84,3421.83
  Top Layer w20: D10.1@1454.74,3558.27 1496.69,3600.21 1513.61,3600.21 1528.81,3615.41 1528.81,3628.21 1537.51,3636.91 R21.2@1538.5,3636.91
  Top Layer w30: C30.2@1394.68,2972.87 1393.69,2972.87 1378.24,2988.32 1378.24,3038.61 D8.1@1377.49,3039.36 1377.49,3041.8 1406.86,3071.17 1406.86,3088.8 ; D10.1@1437.03,3558.27 1454.74,3558.27 1693.31,3558.27 1778.48,3473.1
  Top Layer w40: 1429.35,3088.8 1771.59,2746.55
  Top Layer w80: D10.1@1437.03,3558.27 1442.3,3552.99 1442.3,3434.53 v1@1452.89,3423.95 ; v1@1451.57,3141.95 v1@1452.89,3143.27
  Top Layer w120: v1@1452.89,3143.27 v1@1452.89,3423.95
VCC33: C2.2 C3.2 C20U.2 C20V.2 C20W.2 C26.1 C50.1 C56.1 C59.1 D1.1 D7U.1 D7V.1 D7W.1 J12U.4 J12V.4 J12W.4 R5.2 R14.2 R41.2 R42.2 R61.2 R62.2 R65.2 R68.2 R69.2 R70.2 R76.1 R77.2 R78.1 U1.5 U2.5 U4U.5 U4V.5 U4W.5 U6.4 U10.1 U10.7 U12.5 U12.14 U14.1 | length 1878.2
  Top Layer w8: U12.14@2662.42,3779.75 2660.56,3781.61 2660.56,3817.1 2657.59,3820.07 v1(2657.59,3823.85) 2657.59,3827.64 2662.42,3832.47 C59.1@2662.42,3856.61 ; R69.2@2705.68,2501.36 v1@2705.68,2541.35 ; v1@2711.04,3377.59 R62.2@2711.04,3417.58 ; v1@2759.96,3377.59 R61.2@2759.96,3417.58 ; v1(2764.53,3591.82) 2764.78,3591.57 U12.5@2764.78,3547.46 ; R70.2@2771.43,2502.7 v1@2771.39,2542.73 ; v1(2796.18,2215.84) C56.1@2796.18,2244.84 2800.12,2244.84 2819.1,2263.82 2819.1,2278.83 v1(2821.77,2281.51) ; U14.1@2811.93,2307.1 2811.93,2292.66 2821.77,2282.82 v1(2821.77,2281.51) ; R65.2@2856.72,2261.82 2856.72,2265.76 2848.91,2273.57 2833.5,2273.57 2825.56,2281.51 v1(2821.77,2281.51) ; v1@2856.76,2221.8 R65.2@2856.76,2261.78 ; R68.2@2929.72,2413.4 v1@2929.68,2453.42 ; v1(3109.97,763.83) 3109.97,761.39 3149.99,721.37 R5.2@3150.98,721.37 ; U2.5@3126.34,572.97 v1(3126.34,544.07) 3126.34,541.14 3141.14,526.34 C3.2@3141.14,494.37 ; v3(3672.28,381.38) C20W.2@3725.57,381.38 ; v3(3672.28,1731.38) C20V.2@3725.57,1731.38 ; v3(3672.28,3081.38) C20U.2@3725.57,3081.38
  Top Layer w15: U10.1@1504.07,875 1531.63,875 1550.13,856.5 1614.5,856.5 1613.76,857.25 1577.75,857.25 v1(1577,858) ; U10.7@1504.07,1175 v1(1589,1175) ; v1(1880.84,1379.68) 1881.09,1379.43 1924.89,1379.43 D7V.1@1925.13,1379.18 ; D1.1@2079,1706 2079.5,1706.5 2079.5,1751.5 v1(2080,1752) ; v1(2298,560) 2298.75,559.25 2298.75,519.75 R76.1@2299.5,519 ; D7U.1@2924.65,1311.14 D7U.1@2924.31,1310.79 2973.15,1310.79 v1(2973.58,1310.37) ; D7W.1@2925.31,1442 2925.73,1441.58 2974.58,1441.58 v1(2975,1441.15) ; R77.2@3005.05,351 v1(3051,351) ; R78.1@3008,252 v1(3051,252) ; C2.2@3154.44,3727.22 3154.94,3727.72 v1(3193.74,3727.72) 3232.55,3727.72 U1.5@3233.04,3728.21 ; C20W.2@3726,380.94 3779.33,380.94 3789.6,391.21 U4W.5@3789.6,399.09 ; C20V.2@3726,1730.94 3779.33,1730.94 3789.6,1741.21 U4V.5@3789.6,1749.09 ; C20U.2@3726,3080.94 3779.33,3080.94 3789.6,3091.21 U4U.5@3789.6,3099.09 ; v1(3764.99,1268.37) 3764.5,1268.86 3764.5,1314.24 R14.2@3764.01,1314.73 R14.2@3764.99,1315.72
  Top Layer w17: v1(1635.54,2396.77) 1636.14,2397.37 R41.2@1681.16,2397.37 ; U6.4@1822.77,2464.22 1823,2463.99 1823,2378.84 C26.1@1827.5,2374.34
  other v1: 2856.83,2221.72 2929.61,2453.49 2705.61,2541.42 2771.32,2542.8 2711.11,3377.52 2760.03,3377.52
  other v6: 1799.15,2191.81 1848.9,2191.81 1799.15,2242.81 1848.9,2242.81 1799.15,2292.81
Vdc: C43.1 J1.30 R75.2 | length 255.2
  Top Layer w8: R75.2@2068.99,1619 R75.2@2066.99,1621 2066.99,1553.3 C43.1@2068.3,1552 2082.66,1537.64 J1.30@2245.14,1537.64
VDD: J1.118 U14.10 | length 1330.6
  Top Layer w8: J1.118@2245.14,3049.45 2289.3,3049.45 2361.85,3122 v1(2517,3122) ; v1(2518,2287) 2519.56,2285.44 2673.15,2285.44 2694.81,2307.1 U14.10@2701.7,2307.1
  Bottom Layer w8: v1(2517,3122) 2517.5,3121.5 2517.5,2287.5 v1(2518,2287)
VDD_Driver: C15.1 C16.1 C17.1 C22.1 D3.1 D4.1 J12U.2 J12V.2 J12W.2 R18.2 TP10.1 | length 6922.3
  Top Layer w30: C16.1@1778.6,3882.5 1806.16,3882.5 C16.1@1829.66,3859 ; v1(1829.66,4005.93) v1(1829.66,3975.93) v1(1829.66,3944.93) C16.1@1829.66,3859 ; D4.1@1946,3840.31 1945.25,3841.06 1900.03,3841.06 1884.1,3856.98 C22.1@1884.1,3857.96 1830.7,3857.96 C16.1@1829.66,3859
  Top Layer w50: C15.1@1494.11,3882.82 1510.79,3882.82 1511.38,3883.41 1511.38,3969.45 1521.38,3979.45 TP10.1@1528.65,3979.45
  Top Layer w80: D3.1@1355.84,3944.93 1355.84,3939.71 1361.12,3934.44 1370.27,3934.44 1407.48,3897.23 1480.96,3897.23 1494.11,3884.08 C15.1@1494.11,3882.82 1494.27,3882.66 1778.44,3882.66 C16.1@1778.6,3882.5
  Bottom Layer w30: v1(1829.66,3944.93) v1(1829.66,3975.93) v1(1829.66,4005.93) 1865.71,4041.98 1865.71,4279.71 1993.81,4407.81 3549.85,4407.81 3806,4151.67 3806,3531 J12U.2@3899,3438 3899,2711 3825.84,2637.84 3825.84,2161.16 J12V.2@3899,2088 3899,1555.79 3837.97,1494.75 3837.97,799.03 J12W.2@3899,738
VDDIO: J1.119 U13.1 | length 267.4
  Top Layer w8: J1.119@2379,3080.94 2379.23,3080.71 2645.96,3080.71 U13.1@2646.19,3080.48
Vfb_U: C39U.1 J1.17 R45U.2 | length 351.9
  Top Layer w8: J1.17@2379,1348.66 2558.54,1348.66 C39U.1@2565.7,1341.5 2566.69,1341.5 2597.39,1310.79 2714.55,1310.79 R45U.2@2715.03,1311.27
Vfb_V: C39V.1 J1.20 R45V.2 | length 252.8
  Top Layer w8: R45V.2@2001,1399.59 2067.21,1399.59 C39V.1@2068.3,1398.5 2068.3,1397.52 2085.66,1380.16 J1.20@2245.14,1380.16
Vfb_W: C39W.1 J1.23 R45W.2 | length 362.7
  Top Layer w8: J1.23@2379,1443.15 2533.22,1443.15 2564.72,1474.65 C39W.1@2565.7,1474.65 2566.69,1474.65 2597.41,1443.92 R45W.2@2715.95,1443.92
XRSn: R61.1 R64.2 R66.2 R67.2 U12.4 | length 1463.9
  Top Layer w8: v1(2542.02,2383.99) 2542.08,2383.93 2576.23,2383.93 R67.2@2576.29,2383.87 R66.2@2576.29,2326.94 ; v1(2542.08,2901.64) 2694.22,2901.64 2756.81,2964.24 R64.2@2756.81,2994.33 2756.81,2998.27 2772.37,3013.83 2773.6,3013.83 2783.77,3024 2783.77,3438.3 2776.74,3445.33 2775.51,3445.33 2759.96,3460.89 R61.1@2759.96,3464.82 2759.96,3468.76 2739.19,3489.53 U12.4@2739.19,3547.46
  Bottom Layer w8: v1(2542.02,2383.99) 2542.02,2901.58 v1(2542.08,2901.64)
pads on no net: H1.1 H2.1 H3.1 H4.1 H5.0 H6.0 H7.0 H8.0 J1.9 J1.11 J1.12 J1.14 J1.24 J1.26 J1.28 J1.31 J1.32 J1.33 J1.34 J1.36 J1.37 J1.39 J1.40 J1.41 J1.42 J1.43 J1.44 J1.45 J1.54 J1.57 J1.58 J1.59 J1.60 J1.61 J1.62 J1.63 J1.64 J1.66 J1.67 J1.68 J1.69 J1.70 J1.71 J1.73 J1.76 J1.78 J1.79 J1.81 J1.85 J1.86 J1.87 J1.88 J1.89 J1.90 J1.91 J1.92 J1.93 J1.94 J1.95 J1.96 J1.99 J1.100 J1.101 J1.103 J1.104 J1.105 J1.106 J1.107 J1.108 J1.109 J1.110 J1.113 J1.114 J1.115 J1.116 J1.117 J1.120 J1.181 J1.182 J1.185 J1.186 J4.61 J4.62 J4.121 J4.122 J4.123 J4.124 J4.125 J4.126 J4.127 J4.128 J4.129 J4.130 J4.131 J4.132 J4.133 J4.134 J4.136 J4.137 J4.138 J4.139 J4.140 J4.141 J4.142 J4.143 J4.144 J4.145 J4.146 J4.147 J4.148 J4.149 J4.150 J4.151 J4.152 J4.153 J4.154 J4.155 J4.156 J4.159 J4.160 J4.161 J4.162 J4.163 J4.164 J4.165 J4.166 J4.167 J4.168 J4.169 J4.170 J4.171 J4.172 J4.173 J4.174 J4.175 J4.176 J4.177 J4.178 J7.1 J7.4 J7.6 J7.9 J14.6 LBL1.0 Q1U.MH-1 Q1V.MH-1 Q1W.MH-1 Q2U.MH-1 Q2V.MH-1 Q2W.MH-1 R17. U3.9@606.28,3529.13 U3.9@665.72,3529.13 U6.2 U6.5 U6.6 U6.7 U6.9 U6.10 U6.11 U6.12 U6.14 U6.16 U6.17 U6.18 U6.20 U7.2 U7.5 U7.6 U7.7 U7.9 U7.10 U7.11 U7.12 U7.14 U7.16 U7.17 U7.18 U7.20 U8.2 U8.5 U8.6 U8.7 U8.9 U8.10 U8.11 U8.12 U8.14 U8.16 U8.17 U8.18 U8.20 U9.5 U11.8 U12.3 U12.8 U12.11 U13.6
